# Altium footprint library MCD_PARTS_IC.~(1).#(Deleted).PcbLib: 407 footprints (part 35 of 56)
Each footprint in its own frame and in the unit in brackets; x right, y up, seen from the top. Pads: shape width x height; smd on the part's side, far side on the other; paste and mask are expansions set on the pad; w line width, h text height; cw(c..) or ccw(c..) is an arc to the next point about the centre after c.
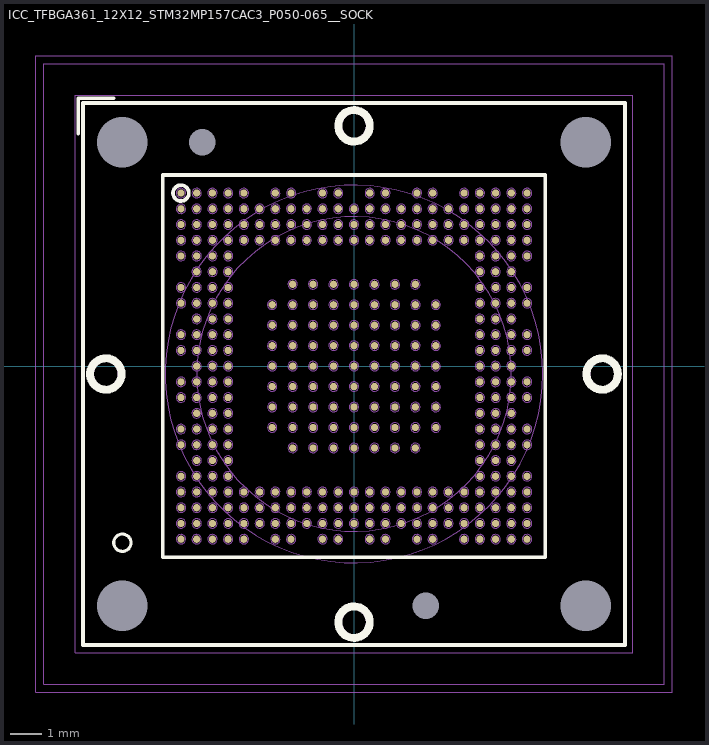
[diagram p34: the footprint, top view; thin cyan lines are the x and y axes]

## ICC_TFBGA361_12X12_STM32MP157CAC3_P050-065__SOCKET_IRONWOOD_CS1828699MF [mm] "MCD-01497"
height 9.9
pads (367):
  round 0 hole 1.61 unplated mask+0.1: 0(-7.363,-7.613) 0(-7.363,7.112) 0(7.362,-7.613) 0(7.362,7.112)
  round 0 hole 0.85 unplated mask+0.1: 0(-4.823,7.112) 0(2.282,-7.613)
  round 0.23 smd mask+0.05: 1A2(-1.95,2.6) 1A3(-1.3,2.6) 1A4(-0.65,2.6) 1A5(0,2.6) 1A6(0.65,2.6) 1A7(1.3,2.6) 1A8(1.95,2.6) 1B1(-2.6,1.95) 1B2(-1.95,1.95) 1B3(-1.3,1.95) 1B4(-0.65,1.95) 1B5(0,1.95) 1B6(0.65,1.95) 1B7(1.3,1.95) 1B8(1.95,1.95) 1B9(2.6,1.95) 1C1(-2.6,1.3) 1C2(-1.95,1.3) 1C3(-1.3,1.3) 1C4(-0.65,1.3) 1C5(0,1.3) 1C6(0.65,1.3) 1C7(1.3,1.3) 1C8(1.95,1.3) 1C9(2.6,1.3) 1D1(-2.6,0.65) 1D2(-1.95,0.65) 1D3(-1.3,0.65) 1D4(-0.65,0.65) 1D5(0,0.65) 1D6(0.65,0.65) 1D7(1.3,0.65) 1D8(1.95,0.65) 1D9(2.6,0.65) 1E1(-2.6,0) 1E2(-1.95,0) 1E3(-1.3,0) 1E4(-0.65,0) 1E5(0,0) 1E6(0.65,0) 1E7(1.3,0) 1E8(1.95,0) 1E9(2.6,0) 1F1(-2.6,-0.65) 1F2(-1.95,-0.65) 1F3(-1.3,-0.65) 1F4(-0.65,-0.65) 1F5(0,-0.65) 1F6(0.65,-0.65) 1F7(1.3,-0.65) 1F8(1.95,-0.65) 1F9(2.6,-0.65) 1G1(-2.6,-1.3) 1G2(-1.95,-1.3) 1G3(-1.3,-1.3) 1G4(-0.65,-1.3) 1G5(0,-1.3) 1G6(0.65,-1.3) 1G7(1.3,-1.3) 1G8(1.95,-1.3) 1G9(2.6,-1.3) 1H1(-2.6,-1.95) 1H2(-1.95,-1.95) 1H3(-1.3,-1.95) 1H4(-0.65,-1.95) 1H5(0,-1.95) 1H6(0.65,-1.95) 1H7(1.3,-1.95) 1H8(1.95,-1.95) 1H9(2.6,-1.95) 1J2(-1.95,-2.6) 1J3(-1.3,-2.6) 1J4(-0.65,-2.6) 1J5(0,-2.6) 1J6(0.65,-2.6) 1J7(1.3,-2.6) 1J8(1.95,-2.6) A1(-5.5,5.5) A2(-5,5.5) A3(-4.5,5.5) A4(-4,5.5) A5(-3.5,5.5) A7(-2.5,5.5) A8(-2,5.5) A10(-1,5.5) A11(-0.5,5.5) A13(0.5,5.5) A14(1,5.5) A16(2,5.5) A17(2.5,5.5) A19(3.5,5.5) A20(4,5.5) A21(4.5,5.5) A22(5,5.5) A23(5.5,5.5) AA1(-5.5,-4.5) AA2(-5,-4.5) AA3(-4.5,-4.5) AA4(-4,-4.5) AA5(-3.5,-4.5) AA6(-3,-4.5) AA7(-2.5,-4.5) AA8(-2,-4.5) AA9(-1.5,-4.5) AA10(-1,-4.5) AA11(-0.5,-4.5) AA12(0,-4.5) AA13(0.5,-4.5) AA14(1,-4.5) AA15(1.5,-4.5) AA16(2,-4.5) AA17(2.5,-4.5) AA18(3,-4.5) AA19(3.5,-4.5) AA20(4,-4.5) AA21(4.5,-4.5) AA22(5,-4.5) AA23(5.5,-4.5) AB1(-5.5,-5) AB2(-5,-5) AB3(-4.5,-5) AB4(-4,-5) AB5(-3.5,-5) AB6(-3,-5) AB7(-2.5,-5) AB8(-2,-5) AB9(-1.5,-5) AB10(-1,-5) AB11(-0.5,-5) AB12(0,-5) AB13(0.5,-5) AB14(1,-5) AB15(1.5,-5) AB16(2,-5) AB17(2.5,-5) AB18(3,-5) AB19(3.5,-5) AB20(4,-5) AB21(4.5,-5) AB22(5,-5) AB23(5.5,-5) AC1(-5.5,-5.5) AC2(-5,-5.5) AC3(-4.5,-5.5) AC4(-4,-5.5) AC5(-3.5,-5.5) AC7(-2.5,-5.5) AC8(-2,-5.5) AC10(-1,-5.5) AC11(-0.5,-5.5) AC13(0.5,-5.5) AC14(1,-5.5) AC16(2,-5.5) AC17(2.5,-5.5) AC19(3.5,-5.5) AC20(4,-5.5) AC21(4.5,-5.5) AC22(5,-5.5) AC23(5.5,-5.5) B1(-5.5,5) B2(-5,5) B3(-4.5,5) B4(-4,5) B5(-3.5,5) B6(-3,5) B7(-2.5,5) B8(-2,5) B9(-1.5,5) B10(-1,5) B11(-0.5,5) B12(0,5) B13(0.5,5) B14(1,5) B15(1.5,5) B16(2,5) B17(2.5,5) B18(3,5) B19(3.5,5) B20(4,5) B21(4.5,5) B22(5,5) B23(5.5,5) C1(-5.5,4.5) C2(-5,4.5) C3(-4.5,4.5) C4(-4,4.5) C5(-3.5,4.5) C6(-3,4.5) C7(-2.5,4.5) C8(-2,4.5) C9(-1.5,4.5) C10(-1,4.5) C11(-0.5,4.5) C12(0,4.5) C13(0.5,4.5) C14(1,4.5) C15(1.5,4.5) C16(2,4.5) C17(2.5,4.5) C18(3,4.5) C19(3.5,4.5) C20(4,4.5) C21(4.5,4.5) C22(5,4.5) C23(5.5,4.5) D1(-5.5,4) D2(-5,4) D3(-4.5,4) D4(-4,4) D5(-3.5,4) D6(-3,4) D7(-2.5,4) D8(-2,4) D9(-1.5,4) D10(-1,4) D11(-0.5,4) D12(0,4) D13(0.5,4) D14(1,4) D15(1.5,4) D16(2,4) D17(2.5,4) D18(3,4) D19(3.5,4) D20(4,4) D21(4.5,4) D22(5,4) D23(5.5,4) E1(-5.5,3.5) E2(-5,3.5) E3(-4.5,3.5) E4(-4,3.5) E20(4,3.5) E21(4.5,3.5) E22(5,3.5) E23(5.5,3.5) F2(-5,3) F3(-4.5,3) F4(-4,3) F20(4,3) F21(4.5,3) F22(5,3) G1(-5.5,2.5) G2(-5,2.5) G3(-4.5,2.5) G4(-4,2.5) G20(4,2.5) G21(4.5,2.5) G22(5,2.5) G23(5.5,2.5) H1(-5.5,2) H2(-5,2) H3(-4.5,2) H4(-4,2) H20(4,2) H21(4.5,2) H22(5,2) H23(5.5,2) J2(-5,1.5) J3(-4.5,1.5) J4(-4,1.5) J20(4,1.5) J21(4.5,1.5) J22(5,1.5) K1(-5.5,1) K2(-5,1) K3(-4.5,1) K4(-4,1) K20(4,1) K21(4.5,1) K22(5,1) K23(5.5,1) L1(-5.5,0.5) L2(-5,0.5) L3(-4.5,0.5) L4(-4,0.5) L20(4,0.5) L21(4.5,0.5) L22(5,0.5) L23(5.5,0.5) M2(-5,0) M3(-4.5,0) M4(-4,0) M20(4,0) M21(4.5,0) M22(5,0) N1(-5.5,-0.5) N2(-5,-0.5) N3(-4.5,-0.5) N4(-4,-0.5) N20(4,-0.5) N21(4.5,-0.5) N22(5,-0.5) N23(5.5,-0.5) P1(-5.5,-1) P2(-5,-1) P3(-4.5,-1) P4(-4,-1) P20(4,-1) P21(4.5,-1) P22(5,-1) P23(5.5,-1) R2(-5,-1.5) R3(-4.5,-1.5) R4(-4,-1.5) R20(4,-1.5) R21(4.5,-1.5) R22(5,-1.5) T1(-5.5,-2) T2(-5,-2) T3(-4.5,-2) T4(-4,-2) T20(4,-2) T21(4.5,-2) T22(5,-2) T23(5.5,-2) U1(-5.5,-2.5) U2(-5,-2.5) U3(-4.5,-2.5) U4(-4,-2.5) U20(4,-2.5) U21(4.5,-2.5) U22(5,-2.5) U23(5.5,-2.5) V2(-5,-3) V3(-4.5,-3) V4(-4,-3) V20(4,-3) V21(4.5,-3) V22(5,-3) W1(-5.5,-3.5) W2(-5,-3.5) W3(-4.5,-3.5) W4(-4,-3.5) W20(4,-3.5) W21(4.5,-3.5) W22(5,-3.5) W23(5.5,-3.5) Y1(-5.5,-4) Y2(-5,-4) Y3(-4.5,-4) Y4(-4,-4) Y5(-3.5,-4) Y6(-3,-4) Y7(-2.5,-4) Y8(-2,-4) Y9(-1.5,-4) Y10(-1,-4) Y11(-0.5,-4) Y12(0,-4) Y13(0.5,-4) Y14(1,-4) Y15(1.5,-4) Y16(2,-4) Y17(2.5,-4) Y18(3,-4) Y19(3.5,-4) Y20(4,-4) Y21(4.5,-4) Y22(5,-4) Y23(5.5,-4)
Top Overlay:
  circle w0.12: c-5.5,5.5 r0.251
  circle w0.1: c-7.363,-5.613 r0.275
  circle w0.25: c-7.888,-0.25 r0.5
  circle w0.25: c0,7.637 r0.5
  circle w0.25: c7.887,-0.25 r0.5
  circle w0.25: c0,-8.138 r0.5
  lines w0.12: -8.763,7.387 -8.763,8.512 -7.638,8.512 ; -8.613,-8.863 8.612,-8.863 8.612,8.362 -8.613,8.362 -8.613,-8.863 ; -6.075,-6.075 6.075,-6.075 6.075,6.075 -6.075,6.075 -6.075,-6.075
Bottom Overlay:
  lines w0.12: -9.863,-10.113 9.862,-10.113 9.862,9.612 -9.863,9.612 -9.863,-10.113
M14-Top Assembly:
  drawing of 380 lines, arcs and shapes, not listed
  text "'.Designator'" at -2,2.75 h0.75
  text "A1" at -5.725,5.35 h0.5
  text "1A2" at -2.3,2.45 h0.5
M15-Bottom Assembly:
  lines w0.01: -9.863,-10.113 9.862,-10.113 9.862,9.612 -9.863,9.612 -9.863,-10.113
M16-Top Courtyard:
  lines w0.01: -8.863,-9.113 -8.863,8.612 8.862,8.612 8.862,-9.113 -8.863,-9.113
M17-Bottom Courtyard:
  lines w0.01: -10.113,-10.363 10.112,-10.363 10.112,9.862 -9.763,9.862 -10.113,9.862 -10.113,-10.363
3D body: height 0.4, standoff 0, extent -8.613,-8.863 8.612,8.362
3D body: height 8.5, standoff 0.4, extent -8.613,-8.863 8.612,8.362
3D body: height 8.51, standoff 8.5, extent -7.637,-5.885 -7.088,-5.337
3D body: height 0.26, standoff -0.04, extent -0.141,-0.148 0.15,0.148
3D body: height 0.26, standoff -0.04, extent -2.741,-0.148 -2.45,0.148
3D body: height 0.26, standoff -0.04, extent -2.091,-0.148 -1.8,0.148
3D body: height 0.26, standoff -0.04, extent -1.441,-0.148 -1.15,0.148
3D body: height 0.26, standoff -0.04, extent -0.791,-0.148 -0.5,0.148
3D body: height 0.26, standoff -0.04, extent 0.509,-0.148 0.8,0.148
3D body: height 0.26, standoff -0.04, extent 1.159,-0.148 1.45,0.148
3D body: height 0.26, standoff -0.04, extent 1.809,-0.148 2.1,0.148
3D body: height 0.26, standoff -0.04, extent 2.459,-0.148 2.75,0.148
3D body: height 0.26, standoff -0.04, extent 2.459,0.502 2.75,0.798
3D body: height 0.26, standoff -0.04, extent 1.809,0.502 2.1,0.798
3D body: height 0.26, standoff -0.04, extent 1.159,0.502 1.45,0.798
3D body: height 0.26, standoff -0.04, extent 0.509,0.502 0.8,0.798
3D body: height 0.26, standoff -0.04, extent -0.791,0.502 -0.5,0.798
3D body: height 0.26, standoff -0.04, extent -1.441,0.502 -1.15,0.798
3D body: height 0.26, standoff -0.04, extent -2.091,0.502 -1.8,0.798
3D body: height 0.26, standoff -0.04, extent -2.741,0.502 -2.45,0.798
3D body: height 0.26, standoff -0.04, extent -0.141,0.502 0.15,0.798
3D body: height 0.26, standoff -0.04, extent 2.459,1.152 2.75,1.448
3D body: height 0.26, standoff -0.04, extent 1.809,1.152 2.1,1.448
3D body: height 0.26, standoff -0.04, extent 1.159,1.152 1.45,1.448
3D body: height 0.26, standoff -0.04, extent 0.509,1.152 0.8,1.448
3D body: height 0.26, standoff -0.04, extent -0.791,1.152 -0.5,1.448
3D body: height 0.26, standoff -0.04, extent -1.441,1.152 -1.15,1.448
3D body: height 0.26, standoff -0.04, extent -2.091,1.152 -1.8,1.448
3D body: height 0.26, standoff -0.04, extent -2.741,1.152 -2.45,1.448
3D body: height 0.26, standoff -0.04, extent -0.141,1.152 0.15,1.448
3D body: height 0.26, standoff -0.04, extent 2.459,1.802 2.75,2.098
3D body: height 0.26, standoff -0.04, extent 1.809,1.802 2.1,2.098
3D body: height 0.26, standoff -0.04, extent 1.159,1.802 1.45,2.098
3D body: height 0.26, standoff -0.04, extent 0.509,1.802 0.8,2.098
3D body: height 0.26, standoff -0.04, extent -0.791,1.802 -0.5,2.098
3D body: height 0.26, standoff -0.04, extent -1.441,1.802 -1.15,2.098
3D body: height 0.26, standoff -0.04, extent -2.091,1.802 -1.8,2.098
3D body: height 0.26, standoff -0.04, extent -2.741,1.802 -2.45,2.098
3D body: height 0.26, standoff -0.04, extent -0.141,1.802 0.15,2.098
3D body: height 0.26, standoff -0.04, extent 1.809,2.452 2.1,2.748
3D body: height 0.26, standoff -0.04, extent 1.159,2.452 1.45,2.748
3D body: height 0.26, standoff -0.04, extent 0.509,2.452 0.8,2.748
3D body: height 0.26, standoff -0.04, extent -0.791,2.452 -0.5,2.748
3D body: height 0.26, standoff -0.04, extent -1.441,2.452 -1.15,2.748
3D body: height 0.26, standoff -0.04, extent -2.091,2.452 -1.8,2.748
3D body: height 0.26, standoff -0.04, extent -0.141,2.452 0.15,2.748
3D body: height 0.26, standoff -0.04, extent 2.459,-0.798 2.75,-0.502
3D body: height 0.26, standoff -0.04, extent 1.809,-0.798 2.1,-0.502
3D body: height 0.26, standoff -0.04, extent 1.159,-0.798 1.45,-0.502
3D body: height 0.26, standoff -0.04, extent 0.509,-0.798 0.8,-0.502
3D body: height 0.26, standoff -0.04, extent -0.791,-0.798 -0.5,-0.502
3D body: height 0.26, standoff -0.04, extent -1.441,-0.798 -1.15,-0.502
3D body: height 0.26, standoff -0.04, extent -2.091,-0.798 -1.8,-0.502
3D body: height 0.26, standoff -0.04, extent -2.741,-0.798 -2.45,-0.502
3D body: height 0.26, standoff -0.04, extent -0.141,-0.798 0.15,-0.502
3D body: height 0.26, standoff -0.04, extent 2.459,-1.448 2.75,-1.152
3D body: height 0.26, standoff -0.04, extent 1.809,-1.448 2.1,-1.152
3D body: height 0.26, standoff -0.04, extent 1.159,-1.448 1.45,-1.152
3D body: height 0.26, standoff -0.04, extent 0.509,-1.448 0.8,-1.152
3D body: height 0.26, standoff -0.04, extent -0.791,-1.448 -0.5,-1.152
3D body: height 0.26, standoff -0.04, extent -1.441,-1.448 -1.15,-1.152
3D body: height 0.26, standoff -0.04, extent -2.091,-1.448 -1.8,-1.152
3D body: height 0.26, standoff -0.04, extent -2.741,-1.448 -2.45,-1.152
3D body: height 0.26, standoff -0.04, extent -0.141,-1.448 0.15,-1.152
3D body: height 0.26, standoff -0.04, extent 2.459,-2.098 2.75,-1.802
3D body: height 0.26, standoff -0.04, extent 1.809,-2.098 2.1,-1.802
3D body: height 0.26, standoff -0.04, extent 1.159,-2.098 1.45,-1.802
3D body: height 0.26, standoff -0.04, extent 0.509,-2.098 0.8,-1.802
3D body: height 0.26, standoff -0.04, extent -0.791,-2.098 -0.5,-1.802
3D body: height 0.26, standoff -0.04, extent -1.441,-2.098 -1.15,-1.802
3D body: height 0.26, standoff -0.04, extent -2.091,-2.098 -1.8,-1.802
3D body: height 0.26, standoff -0.04, extent -2.741,-2.098 -2.45,-1.802
3D body: height 0.26, standoff -0.04, extent -0.141,-2.098 0.15,-1.802
3D body: height 0.26, standoff -0.04, extent 1.809,-2.748 2.1,-2.452
3D body: height 0.26, standoff -0.04, extent 1.159,-2.748 1.45,-2.452
3D body: height 0.26, standoff -0.04, extent 0.509,-2.748 0.8,-2.452
3D body: height 0.26, standoff -0.04, extent -0.791,-2.748 -0.5,-2.452
3D body: height 0.26, standoff -0.04, extent -1.441,-2.748 -1.15,-2.452
3D body: height 0.26, standoff -0.04, extent -2.091,-2.748 -1.8,-2.452
3D body: height 0.26, standoff -0.04, extent -0.141,-2.748 0.15,-2.452
3D body: height 0.26, standoff -0.04, extent -5.641,5.352 -5.35,5.648
3D body: height 0.26, standoff -0.04, extent -5.141,5.352 -4.85,5.648
3D body: height 0.26, standoff -0.04, extent -4.641,5.352 -4.35,5.648
3D body: height 0.26, standoff -0.04, extent -4.141,5.352 -3.85,5.648
3D body: height 0.26, standoff -0.04, extent -3.641,5.352 -3.35,5.648
3D body: height 0.26, standoff -0.04, extent -2.641,5.352 -2.35,5.648
3D body: height 0.26, standoff -0.04, extent -2.141,5.352 -1.85,5.648
3D body: height 0.26, standoff -0.04, extent -1.141,5.352 -0.85,5.648
3D body: height 0.26, standoff -0.04, extent -0.641,5.352 -0.35,5.648
3D body: height 0.26, standoff -0.04, extent 0.359,5.352 0.65,5.648
3D body: height 0.26, standoff -0.04, extent 0.859,5.352 1.15,5.648
3D body: height 0.26, standoff -0.04, extent 1.859,5.352 2.15,5.648
3D body: height 0.26, standoff -0.04, extent 2.359,5.352 2.65,5.648
3D body: height 0.26, standoff -0.04, extent 3.359,5.352 3.65,5.648
3D body: height 0.26, standoff -0.04, extent 3.859,5.352 4.15,5.648
3D body: height 0.26, standoff -0.04, extent 4.359,5.352 4.65,5.648
3D body: height 0.26, standoff -0.04, extent 4.859,5.352 5.15,5.648
3D body: height 0.26, standoff -0.04, extent 5.359,5.352 5.65,5.648
3D body: height 0.26, standoff -0.04, extent 5.359,4.852 5.65,5.148
3D body: height 0.26, standoff -0.04, extent 4.859,4.852 5.15,5.148
3D body: height 0.26, standoff -0.04, extent 4.359,4.852 4.65,5.148
3D body: height 0.26, standoff -0.04, extent 3.859,4.852 4.15,5.148
3D body: height 0.26, standoff -0.04, extent 3.359,4.852 3.65,5.148
3D body: height 0.26, standoff -0.04, extent 2.859,4.852 3.15,5.148
3D body: height 0.26, standoff -0.04, extent 2.359,4.852 2.65,5.148
3D body: height 0.26, standoff -0.04, extent 1.859,4.852 2.15,5.148
3D body: height 0.26, standoff -0.04, extent 1.359,4.852 1.65,5.148
3D body: height 0.26, standoff -0.04, extent 0.859,4.852 1.15,5.148
3D body: height 0.26, standoff -0.04, extent 0.359,4.852 0.65,5.148
3D body: height 0.26, standoff -0.04, extent -0.141,4.852 0.15,5.148
3D body: height 0.26, standoff -0.04, extent -0.641,4.852 -0.35,5.148
3D body: height 0.26, standoff -0.04, extent -1.141,4.852 -0.85,5.148
3D body: height 0.26, standoff -0.04, extent -1.641,4.852 -1.35,5.148
3D body: height 0.26, standoff -0.04, extent -2.141,4.852 -1.85,5.148
3D body: height 0.26, standoff -0.04, extent -2.641,4.852 -2.35,5.148
3D body: height 0.26, standoff -0.04, extent -3.141,4.852 -2.85,5.148
3D body: height 0.26, standoff -0.04, extent -3.641,4.852 -3.35,5.148
3D body: height 0.26, standoff -0.04, extent -4.141,4.852 -3.85,5.148
3D body: height 0.26, standoff -0.04, extent -4.641,4.852 -4.35,5.148
3D body: height 0.26, standoff -0.04, extent -5.141,4.852 -4.85,5.148
3D body: height 0.26, standoff -0.04, extent -5.641,4.852 -5.35,5.148
3D body: height 0.26, standoff -0.04, extent 5.359,4.352 5.65,4.648
3D body: height 0.26, standoff -0.04, extent 4.859,4.352 5.15,4.648
3D body: height 0.26, standoff -0.04, extent 4.359,4.352 4.65,4.648
3D body: height 0.26, standoff -0.04, extent 3.859,4.352 4.15,4.648
3D body: height 0.26, standoff -0.04, extent 3.359,4.352 3.65,4.648
3D body: height 0.26, standoff -0.04, extent 2.859,4.352 3.15,4.648
3D body: height 0.26, standoff -0.04, extent 2.359,4.352 2.65,4.648
3D body: height 0.26, standoff -0.04, extent 1.859,4.352 2.15,4.648
3D body: height 0.26, standoff -0.04, extent 1.359,4.352 1.65,4.648
3D body: height 0.26, standoff -0.04, extent 0.859,4.352 1.15,4.648
3D body: height 0.26, standoff -0.04, extent 0.359,4.352 0.65,4.648
3D body: height 0.26, standoff -0.04, extent -0.141,4.352 0.15,4.648
3D body: height 0.26, standoff -0.04, extent -0.641,4.352 -0.35,4.648
3D body: height 0.26, standoff -0.04, extent -1.141,4.352 -0.85,4.648
3D body: height 0.26, standoff -0.04, extent -1.641,4.352 -1.35,4.648
3D body: height 0.26, standoff -0.04, extent -2.141,4.352 -1.85,4.648
3D body: height 0.26, standoff -0.04, extent -2.641,4.352 -2.35,4.648
3D body: height 0.26, standoff -0.04, extent -3.141,4.352 -2.85,4.648
3D body: height 0.26, standoff -0.04, extent -3.641,4.352 -3.35,4.648
3D body: height 0.26, standoff -0.04, extent -4.141,4.352 -3.85,4.648
3D body: height 0.26, standoff -0.04, extent -4.641,4.352 -4.35,4.648
3D body: height 0.26, standoff -0.04, extent -5.141,4.352 -4.85,4.648
3D body: height 0.26, standoff -0.04, extent -5.641,4.352 -5.35,4.648
3D body: height 0.26, standoff -0.04, extent 5.359,3.852 5.65,4.148
3D body: height 0.26, standoff -0.04, extent 4.859,3.852 5.15,4.148
3D body: height 0.26, standoff -0.04, extent 4.359,3.852 4.65,4.148
3D body: height 0.26, standoff -0.04, extent 3.859,3.852 4.15,4.148
3D body: height 0.26, standoff -0.04, extent 3.359,3.852 3.65,4.148
3D body: height 0.26, standoff -0.04, extent 2.859,3.852 3.15,4.148
3D body: height 0.26, standoff -0.04, extent 2.359,3.852 2.65,4.148
3D body: height 0.26, standoff -0.04, extent 1.859,3.852 2.15,4.148
3D body: height 0.26, standoff -0.04, extent 1.359,3.852 1.65,4.148
3D body: height 0.26, standoff -0.04, extent 0.859,3.852 1.15,4.148
3D body: height 0.26, standoff -0.04, extent 0.359,3.852 0.65,4.148
3D body: height 0.26, standoff -0.04, extent -0.141,3.852 0.15,4.148
3D body: height 0.26, standoff -0.04, extent -0.641,3.852 -0.35,4.148
3D body: height 0.26, standoff -0.04, extent -1.141,3.852 -0.85,4.148
3D body: height 0.26, standoff -0.04, extent -1.641,3.852 -1.35,4.148
3D body: height 0.26, standoff -0.04, extent -2.141,3.852 -1.85,4.148
3D body: height 0.26, standoff -0.04, extent -2.641,3.852 -2.35,4.148
3D body: height 0.26, standoff -0.04, extent -3.141,3.852 -2.85,4.148
3D body: height 0.26, standoff -0.04, extent -3.641,3.852 -3.35,4.148
3D body: height 0.26, standoff -0.04, extent -4.141,3.852 -3.85,4.148
3D body: height 0.26, standoff -0.04, extent -4.641,3.852 -4.35,4.148
3D body: height 0.26, standoff -0.04, extent -5.141,3.852 -4.85,4.148
3D body: height 0.26, standoff -0.04, extent -5.641,3.852 -5.35,4.148
3D body: height 0.26, standoff -0.04, extent 5.359,-4.148 5.65,-3.852
3D body: height 0.26, standoff -0.04, extent 4.859,-4.148 5.15,-3.852
3D body: height 0.26, standoff -0.04, extent 4.359,-4.148 4.65,-3.852
3D body: height 0.26, standoff -0.04, extent 3.859,-4.148 4.15,-3.852
3D body: height 0.26, standoff -0.04, extent 3.359,-4.148 3.65,-3.852
3D body: height 0.26, standoff -0.04, extent 2.859,-4.148 3.15,-3.852
3D body: height 0.26, standoff -0.04, extent 2.359,-4.148 2.65,-3.852
3D body: height 0.26, standoff -0.04, extent 1.859,-4.148 2.15,-3.852
3D body: height 0.26, standoff -0.04, extent 1.359,-4.148 1.65,-3.852
3D body: height 0.26, standoff -0.04, extent 0.859,-4.148 1.15,-3.852
3D body: height 0.26, standoff -0.04, extent 0.359,-4.148 0.65,-3.852
3D body: height 0.26, standoff -0.04, extent -0.141,-4.148 0.15,-3.852
3D body: height 0.26, standoff -0.04, extent -0.641,-4.148 -0.35,-3.852
3D body: height 0.26, standoff -0.04, extent -1.141,-4.148 -0.85,-3.852
3D body: height 0.26, standoff -0.04, extent -1.641,-4.148 -1.35,-3.852
3D body: height 0.26, standoff -0.04, extent -2.141,-4.148 -1.85,-3.852
3D body: height 0.26, standoff -0.04, extent -2.641,-4.148 -2.35,-3.852
3D body: height 0.26, standoff -0.04, extent -3.141,-4.148 -2.85,-3.852
3D body: height 0.26, standoff -0.04, extent -3.641,-4.148 -3.35,-3.852
3D body: height 0.26, standoff -0.04, extent -4.141,-4.148 -3.85,-3.852
3D body: height 0.26, standoff -0.04, extent -4.641,-4.148 -4.35,-3.852
3D body: height 0.26, standoff -0.04, extent -5.141,-4.148 -4.85,-3.852
3D body: height 0.26, standoff -0.04, extent -5.641,-4.148 -5.35,-3.852
3D body: height 0.26, standoff -0.04, extent 5.359,-4.648 5.65,-4.352
3D body: height 0.26, standoff -0.04, extent 4.859,-4.648 5.15,-4.352
3D body: height 0.26, standoff -0.04, extent 4.359,-4.648 4.65,-4.352
3D body: height 0.26, standoff -0.04, extent 3.859,-4.648 4.15,-4.352
3D body: height 0.26, standoff -0.04, extent 3.359,-4.648 3.65,-4.352
3D body: height 0.26, standoff -0.04, extent 2.859,-4.648 3.15,-4.352
3D body: height 0.26, standoff -0.04, extent 2.359,-4.648 2.65,-4.352
3D body: height 0.26, standoff -0.04, extent 1.859,-4.648 2.15,-4.352
3D body: height 0.26, standoff -0.04, extent 1.359,-4.648 1.65,-4.352
3D body: height 0.26, standoff -0.04, extent 0.859,-4.648 1.15,-4.352
3D body: height 0.26, standoff -0.04, extent 0.359,-4.648 0.65,-4.352
3D body: height 0.26, standoff -0.04, extent -0.141,-4.648 0.15,-4.352
3D body: height 0.26, standoff -0.04, extent -0.641,-4.648 -0.35,-4.352
3D body: height 0.26, standoff -0.04, extent -1.141,-4.648 -0.85,-4.352
3D body: height 0.26, standoff -0.04, extent -1.641,-4.648 -1.35,-4.352
3D body: height 0.26, standoff -0.04, extent -2.141,-4.648 -1.85,-4.352
3D body: height 0.26, standoff -0.04, extent -2.641,-4.648 -2.35,-4.352
3D body: height 0.26, standoff -0.04, extent -3.141,-4.648 -2.85,-4.352
3D body: height 0.26, standoff -0.04, extent -3.641,-4.648 -3.35,-4.352
3D body: height 0.26, standoff -0.04, extent -4.141,-4.648 -3.85,-4.352
3D body: height 0.26, standoff -0.04, extent -4.641,-4.648 -4.35,-4.352
3D body: height 0.26, standoff -0.04, extent -5.141,-4.648 -4.85,-4.352
3D body: height 0.26, standoff -0.04, extent -5.641,-4.648 -5.35,-4.352
3D body: height 0.26, standoff -0.04, extent 5.359,-5.148 5.65,-4.852
3D body: height 0.26, standoff -0.04, extent 4.859,-5.148 5.15,-4.852
3D body: height 0.26, standoff -0.04, extent 4.359,-5.148 4.65,-4.852
3D body: height 0.26, standoff -0.04, extent 3.859,-5.148 4.15,-4.852
3D body: height 0.26, standoff -0.04, extent 3.359,-5.148 3.65,-4.852
3D body: height 0.26, standoff -0.04, extent 2.859,-5.148 3.15,-4.852
3D body: height 0.26, standoff -0.04, extent 2.359,-5.148 2.65,-4.852
3D body: height 0.26, standoff -0.04, extent 1.859,-5.148 2.15,-4.852
3D body: height 0.26, standoff -0.04, extent 1.359,-5.148 1.65,-4.852
3D body: height 0.26, standoff -0.04, extent 0.859,-5.148 1.15,-4.852
3D body: height 0.26, standoff -0.04, extent 0.359,-5.148 0.65,-4.852
3D body: height 0.26, standoff -0.04, extent -0.141,-5.148 0.15,-4.852
3D body: height 0.26, standoff -0.04, extent -0.641,-5.148 -0.35,-4.852
3D body: height 0.26, standoff -0.04, extent -1.141,-5.148 -0.85,-4.852
3D body: height 0.26, standoff -0.04, extent -1.641,-5.148 -1.35,-4.852
3D body: height 0.26, standoff -0.04, extent -2.141,-5.148 -1.85,-4.852
3D body: height 0.26, standoff -0.04, extent -2.641,-5.148 -2.35,-4.852
3D body: height 0.26, standoff -0.04, extent -3.141,-5.148 -2.85,-4.852
3D body: height 0.26, standoff -0.04, extent -3.641,-5.148 -3.35,-4.852
3D body: height 0.26, standoff -0.04, extent -4.141,-5.148 -3.85,-4.852
3D body: height 0.26, standoff -0.04, extent -4.641,-5.148 -4.35,-4.852
3D body: height 0.26, standoff -0.04, extent -5.141,-5.148 -4.85,-4.852
3D body: height 0.26, standoff -0.04, extent -5.641,-5.148 -5.35,-4.852
3D body: height 0.26, standoff -0.04, extent 5.359,-5.648 5.65,-5.352
3D body: height 0.26, standoff -0.04, extent 4.859,-5.648 5.15,-5.352
3D body: height 0.26, standoff -0.04, extent 4.359,-5.648 4.65,-5.352
3D body: height 0.26, standoff -0.04, extent 3.859,-5.648 4.15,-5.352
3D body: height 0.26, standoff -0.04, extent 3.359,-5.648 3.65,-5.352
3D body: height 0.26, standoff -0.04, extent 2.359,-5.648 2.65,-5.352
3D body: height 0.26, standoff -0.04, extent 1.859,-5.648 2.15,-5.352
3D body: height 0.26, standoff -0.04, extent 0.859,-5.648 1.15,-5.352
3D body: height 0.26, standoff -0.04, extent 0.359,-5.648 0.65,-5.352
3D body: height 0.26, standoff -0.04, extent -0.641,-5.648 -0.35,-5.352
3D body: height 0.26, standoff -0.04, extent -1.141,-5.648 -0.85,-5.352
3D body: height 0.26, standoff -0.04, extent -2.141,-5.648 -1.85,-5.352
3D body: height 0.26, standoff -0.04, extent -2.641,-5.648 -2.35,-5.352
3D body: height 0.26, standoff -0.04, extent -3.641,-5.648 -3.35,-5.352
3D body: height 0.26, standoff -0.04, extent -4.141,-5.648 -3.85,-5.352
3D body: height 0.26, standoff -0.04, extent -4.641,-5.648 -4.35,-5.352
3D body: height 0.26, standoff -0.04, extent -5.141,-5.648 -4.85,-5.352
3D body: height 0.26, standoff -0.04, extent -5.641,-5.648 -5.35,-5.352
3D body: height 0.26, standoff -0.04, extent -5.648,3.359 -5.352,3.65
3D body: height 0.26, standoff -0.04, extent -5.648,2.359 -5.352,2.65
3D body: height 0.26, standoff -0.04, extent -5.648,1.859 -5.352,2.15
3D body: height 0.26, standoff -0.04, extent -5.648,0.859 -5.352,1.15
3D body: height 0.26, standoff -0.04, extent -5.648,0.359 -5.352,0.65
3D body: height 0.26, standoff -0.04, extent -5.648,-0.641 -5.352,-0.35
3D body: height 0.26, standoff -0.04, extent -5.648,-1.141 -5.352,-0.85
3D body: height 0.26, standoff -0.04, extent -5.648,-2.141 -5.352,-1.85
3D body: height 0.26, standoff -0.04, extent -5.648,-2.641 -5.352,-2.35
3D body: height 0.26, standoff -0.04, extent -5.648,-3.641 -5.352,-3.35
3D body: height 0.26, standoff -0.04, extent -5.148,-3.641 -4.852,-3.35
3D body: height 0.26, standoff -0.04, extent -5.148,-3.141 -4.852,-2.85
3D body: height 0.26, standoff -0.04, extent -5.148,-2.641 -4.852,-2.35
3D body: height 0.26, standoff -0.04, extent -5.148,-2.141 -4.852,-1.85
3D body: height 0.26, standoff -0.04, extent -5.148,-1.641 -4.852,-1.35
3D body: height 0.26, standoff -0.04, extent -5.148,-1.141 -4.852,-0.85
3D body: height 0.26, standoff -0.04, extent -5.148,-0.641 -4.852,-0.35
3D body: height 0.26, standoff -0.04, extent -5.148,-0.141 -4.852,0.15
3D body: height 0.26, standoff -0.04, extent -5.148,0.359 -4.852,0.65
3D body: height 0.26, standoff -0.04, extent -5.148,0.859 -4.852,1.15
3D body: height 0.26, standoff -0.04, extent -5.148,1.359 -4.852,1.65
3D body: height 0.26, standoff -0.04, extent -5.148,1.859 -4.852,2.15
3D body: height 0.26, standoff -0.04, extent -5.148,2.359 -4.852,2.65
3D body: height 0.26, standoff -0.04, extent -5.148,2.859 -4.852,3.15
3D body: height 0.26, standoff -0.04, extent -5.148,3.359 -4.852,3.65
3D body: height 0.26, standoff -0.04, extent -4.648,-3.641 -4.352,-3.35
3D body: height 0.26, standoff -0.04, extent -4.648,-3.141 -4.352,-2.85
3D body: height 0.26, standoff -0.04, extent -4.648,-2.641 -4.352,-2.35
3D body: height 0.26, standoff -0.04, extent -4.648,-2.141 -4.352,-1.85
3D body: height 0.26, standoff -0.04, extent -4.648,-1.641 -4.352,-1.35
3D body: height 0.26, standoff -0.04, extent -4.648,-1.141 -4.352,-0.85
3D body: height 0.26, standoff -0.04, extent -4.648,-0.641 -4.352,-0.35
3D body: height 0.26, standoff -0.04, extent -4.648,-0.141 -4.352,0.15
3D body: height 0.26, standoff -0.04, extent -4.648,0.359 -4.352,0.65
3D body: height 0.26, standoff -0.04, extent -4.648,0.859 -4.352,1.15
3D body: height 0.26, standoff -0.04, extent -4.648,1.359 -4.352,1.65
3D body: height 0.26, standoff -0.04, extent -4.648,1.859 -4.352,2.15
3D body: height 0.26, standoff -0.04, extent -4.648,2.359 -4.352,2.65
3D body: height 0.26, standoff -0.04, extent -4.648,2.859 -4.352,3.15
3D body: height 0.26, standoff -0.04, extent -4.648,3.359 -4.352,3.65
3D body: height 0.26, standoff -0.04, extent -4.148,-3.641 -3.852,-3.35
3D body: height 0.26, standoff -0.04, extent -4.148,-3.141 -3.852,-2.85
3D body: height 0.26, standoff -0.04, extent -4.148,-2.641 -3.852,-2.35
3D body: height 0.26, standoff -0.04, extent -4.148,-2.141 -3.852,-1.85
3D body: height 0.26, standoff -0.04, extent -4.148,-1.641 -3.852,-1.35
3D body: height 0.26, standoff -0.04, extent -4.148,-1.141 -3.852,-0.85
3D body: height 0.26, standoff -0.04, extent -4.148,-0.641 -3.852,-0.35
3D body: height 0.26, standoff -0.04, extent -4.148,-0.141 -3.852,0.15
3D body: height 0.26, standoff -0.04, extent -4.148,0.359 -3.852,0.65
3D body: height 0.26, standoff -0.04, extent -4.148,0.859 -3.852,1.15
3D body: height 0.26, standoff -0.04, extent -4.148,1.359 -3.852,1.65
3D body: height 0.26, standoff -0.04, extent -4.148,1.859 -3.852,2.15
3D body: height 0.26, standoff -0.04, extent -4.148,2.359 -3.852,2.65
3D body: height 0.26, standoff -0.04, extent -4.148,2.859 -3.852,3.15
3D body: height 0.26, standoff -0.04, extent -4.148,3.359 -3.852,3.65
3D body: height 0.26, standoff -0.04, extent 5.352,-3.641 5.648,-3.35
3D body: height 0.26, standoff -0.04, extent 5.352,-2.641 5.648,-2.35
3D body: height 0.26, standoff -0.04, extent 5.352,-2.141 5.648,-1.85
3D body: height 0.26, standoff -0.04, extent 5.352,-1.141 5.648,-0.85
3D body: height 0.26, standoff -0.04, extent 5.352,-0.641 5.648,-0.35
3D body: height 0.26, standoff -0.04, extent 5.352,0.359 5.648,0.65
3D body: height 0.26, standoff -0.04, extent 5.352,0.859 5.648,1.15
3D body: height 0.26, standoff -0.04, extent 5.352,1.859 5.648,2.15
3D body: height 0.26, standoff -0.04, extent 5.352,2.359 5.648,2.65
3D body: height 0.26, standoff -0.04, extent 5.352,3.359 5.648,3.65
3D body: height 0.26, standoff -0.04, extent 4.852,-3.641 5.148,-3.35
3D body: height 0.26, standoff -0.04, extent 4.852,-3.141 5.148,-2.85
3D body: height 0.26, standoff -0.04, extent 4.852,-2.641 5.148,-2.35
3D body: height 0.26, standoff -0.04, extent 4.852,-2.141 5.148,-1.85
3D body: height 0.26, standoff -0.04, extent 4.852,-1.641 5.148,-1.35
3D body: height 0.26, standoff -0.04, extent 4.852,-1.141 5.148,-0.85
3D body: height 0.26, standoff -0.04, extent 4.852,-0.641 5.148,-0.35
3D body: height 0.26, standoff -0.04, extent 4.852,-0.141 5.148,0.15
3D body: height 0.26, standoff -0.04, extent 4.852,0.359 5.148,0.65
3D body: height 0.26, standoff -0.04, extent 4.852,0.859 5.148,1.15
3D body: height 0.26, standoff -0.04, extent 4.852,1.359 5.148,1.65
3D body: height 0.26, standoff -0.04, extent 4.852,1.859 5.148,2.15
3D body: height 0.26, standoff -0.04, extent 4.852,2.359 5.148,2.65
3D body: height 0.26, standoff -0.04, extent 4.852,2.859 5.148,3.15
3D body: height 0.26, standoff -0.04, extent 4.852,3.359 5.148,3.65
3D body: height 0.26, standoff -0.04, extent 4.352,-3.641 4.648,-3.35
3D body: height 0.26, standoff -0.04, extent 4.352,-3.141 4.648,-2.85
3D body: height 0.26, standoff -0.04, extent 4.352,-2.641 4.648,-2.35
3D body: height 0.26, standoff -0.04, extent 4.352,-2.141 4.648,-1.85
3D body: height 0.26, standoff -0.04, extent 4.352,-1.641 4.648,-1.35
3D body: height 0.26, standoff -0.04, extent 4.352,-1.141 4.648,-0.85
3D body: height 0.26, standoff -0.04, extent 4.352,-0.641 4.648,-0.35
3D body: height 0.26, standoff -0.04, extent 4.352,-0.141 4.648,0.15
3D body: height 0.26, standoff -0.04, extent 4.352,0.359 4.648,0.65
3D body: height 0.26, standoff -0.04, extent 4.352,0.859 4.648,1.15
3D body: height 0.26, standoff -0.04, extent 4.352,1.359 4.648,1.65
3D body: height 0.26, standoff -0.04, extent 4.352,1.859 4.648,2.15
3D body: height 0.26, standoff -0.04, extent 4.352,2.359 4.648,2.65
3D body: height 0.26, standoff -0.04, extent 4.352,2.859 4.648,3.15
3D body: height 0.26, standoff -0.04, extent 4.352,3.359 4.648,3.65
3D body: height 0.26, standoff -0.04, extent 3.852,-3.641 4.148,-3.35
3D body: height 0.26, standoff -0.04, extent 3.852,-3.141 4.148,-2.85
3D body: height 0.26, standoff -0.04, extent 3.852,-2.641 4.148,-2.35
3D body: height 0.26, standoff -0.04, extent 3.852,-2.141 4.148,-1.85
3D body: height 0.26, standoff -0.04, extent 3.852,-1.641 4.148,-1.35
3D body: height 0.26, standoff -0.04, extent 3.852,-1.141 4.148,-0.85
3D body: height 0.26, standoff -0.04, extent 3.852,-0.641 4.148,-0.35
3D body: height 0.26, standoff -0.04, extent 3.852,-0.141 4.148,0.15
3D body: height 0.26, standoff -0.04, extent 3.852,0.359 4.148,0.65
3D body: height 0.26, standoff -0.04, extent 3.852,0.859 4.148,1.15
3D body: height 0.26, standoff -0.04, extent 3.852,1.359 4.148,1.65
3D body: height 0.26, standoff -0.04, extent 3.852,1.859 4.148,2.15
3D body: height 0.26, standoff -0.04, extent 3.852,2.359 4.148,2.65
3D body: height 0.26, standoff -0.04, extent 3.852,2.859 4.148,3.15
3D body: height 0.26, standoff -0.04, extent 3.852,3.359 4.148,3.65
3D body: height 1.2, standoff 0.2, extent -6.075,-6.075 6.075,6.075
3D body: height 1.21, standoff 1.2, extent -5.798,5.201 -5.2,5.799
3D body: height 9.2, standoff 8.5, extent -6,-6.25 6,5.75
3D body: height 9.21, standoff 8.5, extent -5,-5.25 5,4.75
3D body: height 9.91, standoff 8.5, extent -8.287,-0.647 -7.488,0.15
3D body: height 9.9, standoff 8.5, extent -8.437,-0.796 -7.339,0.3
3D body: height 9.9, standoff 8.5, extent -0.549,7.092 0.549,8.188
3D body: height 9.91, standoff 8.5, extent -0.399,7.241 0.399,8.038
3D body: height 9.9, standoff 8.5, extent 7.338,-0.796 8.436,0.3
3D body: height 9.91, standoff 8.5, extent 7.488,-0.647 8.287,0.15
3D body: height 9.9, standoff 8.5, extent -0.549,-8.683 0.549,-7.587
3D body: height 9.91, standoff 8.5, extent -0.399,-8.534 0.399,-7.737
3D body: height 1.6, standoff 0, extent -9.863,-10.113 9.862,9.612
3D body: height 7.95, standoff 1.6, extent -9.863,-10.113 9.862,9.612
